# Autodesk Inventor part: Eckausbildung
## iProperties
Created: 2007-06
Part Number: Eckausbildung
Document SubType Name: Sheet Metal
Designer: rj
Author: rj
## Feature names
1. Grobblech1
2. Ausklinkung1
3. Ecke1
4. Ausklinkung2
5. Ecke2
6. Ausklinkung3
